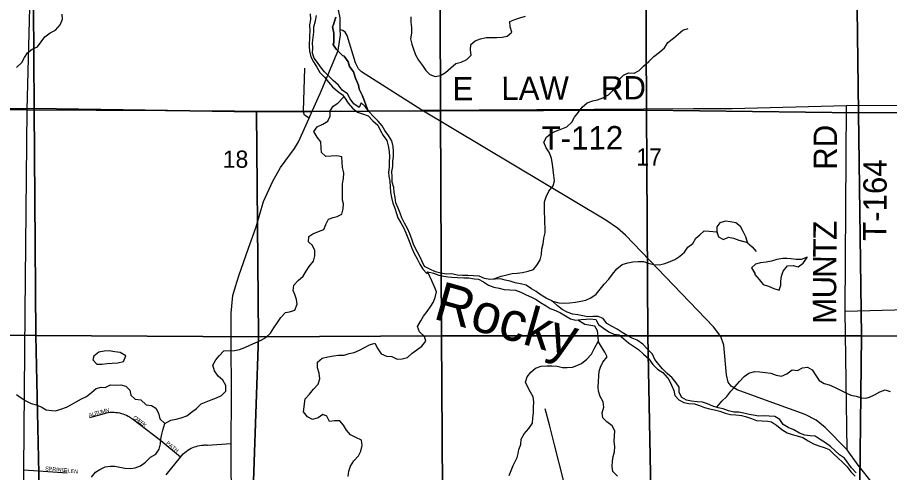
# Model space of a CAD drawing. Extents: x 1985906 to 2277390, y 930619 to 1324581.
# Drawn here: x 2123724 to 2134931, y 1169867 to 1175711 of the extents above; entities that cross this region are included whole.
import ezdxf

# ---------------------------------------------------------------- set-up
doc = ezdxf.new("R2010")
doc.units = 0
for name, color, linetype in [('GM_X_County_Road', 7, 'Continuous'), ('GM_X_Major_River', 7, 'Continuous'), ('GM_X_Major_River_Text', 7, 'Continuous'), ('GM_X_Minor_Lake', 7, 'Continuous'), ('GM_X_Minor_River', 7, 'Continuous'), ('GM_X_Section', 7, 'Continuous'), ('GM_X_Section_Text', 7, 'Continuous'), ('GM_X_State_Route', 7, 'Continuous'), ('GM_X_Township_Road', 7, 'Continuous'), ('GM_X_Township_Road_Text', 7, 'Continuous'), ('GM_X_Township_Subdivision', 7, 'Continuous'), ('GM_X_Township_Subdivision_Text', 7, 'Continuous')]:
    doc.layers.add(name, color=color, linetype=linetype)

msp = doc.modelspace()

# ---------------------------------------------------------------- linework, layer by layer
at = {"layer": 'GM_X_County_Road'}
for points in [[(2123773, 1166123), (2123795, 1166134), (2123816, 1166179), (2123825, 1166243), (2123823, 1166364), (2123796, 1168159), (2123801, 1169024), (2123808, 1169901), (2123825, 1171926), (2123847, 1174524), (2123893, 1176169), (2123892, 1176328), (2123891, 1176487), (2123884, 1177498), (2123887, 1178763), (2123908, 1179927)], [(2134713, 1169730), (2134529, 1169962), (2134386, 1170157), (2134102, 1170445), (2133990, 1170541), (2133849, 1170614), (2133290, 1170814), (2132971, 1170930), (2132894, 1170978), (2132858, 1171030), (2132837, 1171124), (2132801, 1171503), (2132762, 1171615), (2132669, 1171737), (2131538, 1172915), (2131435, 1173007), (2131284, 1173110), (2128920, 1174522), (2128145, 1175013), (2128107, 1175051), (2128070, 1175129), (2127962, 1175480), (2127936, 1175522), (2127906, 1175542), (2127873, 1175554)]]:
    msp.add_lwpolyline(points, dxfattribs=at)
at = {"layer": 'GM_X_Major_River'}
for points in [[(2127485, 1175756), (2127491, 1175687), (2127478, 1175615), (2127480, 1175545), (2127478, 1175470), (2127473, 1175342), (2127477, 1175277), (2127494, 1175207), (2127530, 1175143), (2127570, 1175074), (2127608, 1175006), (2127670, 1174943), (2127721, 1174882), (2127771, 1174820), (2127837, 1174765), (2127903, 1174717), (2127925, 1174684), (2127975, 1174612), (2128029, 1174545), (2128093, 1174493), (2128159, 1174474), (2128231, 1174446), (2128291, 1174385), (2128354, 1174326), (2128386, 1174262), (2128424, 1174196), (2128470, 1174133), (2128490, 1174063), (2128499, 1173992)], [(2128842, 1172735), (2128812, 1172799), (2128792, 1172866), (2128767, 1172932), (2128735, 1173003), (2128697, 1173071), (2128665, 1173138), (2128642, 1173198), (2128616, 1173264), (2128586, 1173331), (2128578, 1173399), (2128567, 1173466), (2128561, 1173528), (2128539, 1173596), (2128540, 1173665), (2128536, 1173733), (2128550, 1173797), (2128547, 1173865), (2128555, 1173926), (2128555, 1173990), (2128552, 1174056), (2128534, 1174129), (2128494, 1174197), (2128446, 1174260), (2128409, 1174318), (2128361, 1174381), (2128305, 1174437), (2128239, 1174504), (2128193, 1174568), (2128141, 1174613), (2128115, 1174557), (2128049, 1174601), (2127999, 1174666), (2127965, 1174730), (2127899, 1174779), (2127848, 1174842), (2127780, 1174900), (2127724, 1174957), (2127670, 1175011), (2127618, 1175078), (2127582, 1175132), (2127538, 1175187), (2127515, 1175253), (2127519, 1175321), (2127517, 1175386), (2127534, 1175522), (2127532, 1175591), (2127553, 1175667), (2127565, 1175737)], [(2128499, 1173992), (2128505, 1173922), (2128501, 1173856), (2128502, 1173789), (2128494, 1173725), (2128498, 1173675), (2128509, 1173609), (2128513, 1173536), (2128519, 1173468), (2128532, 1173399), (2128548, 1173327), (2128572, 1173263), (2128596, 1173194), (2128613, 1173140), (2128651, 1173075), (2128687, 1173013), (2128717, 1172946), (2128742, 1172880), (2128768, 1172816), (2128794, 1172747), (2128824, 1172679), (2128859, 1172612), (2128897, 1172544), (2128933, 1172481), (2128983, 1172425), (2128999, 1172443), (2129071, 1172426), (2129139, 1172404), (2129203, 1172389), (2129253, 1172379), (2129307, 1172377), (2129380, 1172372), (2129460, 1172368), (2129526, 1172367), (2129598, 1172355), (2129648, 1172349), (2129712, 1172316), (2129778, 1172274), (2129848, 1172249), (2129916, 1172235), (2129979, 1172220), (2130051, 1172214), (2130125, 1172210), (2130195, 1172185), (2130261, 1172149), (2130329, 1172120), (2130391, 1172088), (2130445, 1172053), (2130517, 1172008), (2130571, 1171976), (2130637, 1171950), (2130703, 1171919), (2130769, 1171881), (2130833, 1171842), (2130901, 1171822), (2130969, 1171831), (2131034, 1171837), (2131086, 1171841), (2131158, 1171834), (2131192, 1171770), (2131256, 1171721), (2131322, 1171675), (2131388, 1171644), (2131456, 1171636), (2131518, 1171583), (2131578, 1171533), (2131640, 1171490), (2131706, 1171446), (2131769, 1171389), (2131839, 1171326), (2131889, 1171254), (2131951, 1171193), (2132019, 1171150), (2132075, 1171088), (2132095, 1171064), (2132130, 1170991), (2132158, 1170923), (2132174, 1170856), (2132224, 1170800), (2132288, 1170767), (2132352, 1170753), (2132426, 1170750), (2132490, 1170730), (2132554, 1170702), (2132618, 1170685), (2132682, 1170673), (2132751, 1170656), (2132821, 1170630), (2132889, 1170613), (2132955, 1170607), (2133027, 1170599), (2133095, 1170582), (2133159, 1170560), (2133223, 1170537), (2133293, 1170533), (2133366, 1170526), (2133416, 1170518), (2133480, 1170476), (2133546, 1170419), (2133614, 1170378), (2133682, 1170356)], [(2134503, 1169863), (2134442, 1169930), (2134354, 1170051), (2134288, 1170093), (2134230, 1170152), (2134172, 1170200), (2134108, 1170247), (2134040, 1170290), (2133976, 1170336), (2133910, 1170339), (2133842, 1170347), (2133772, 1170371), (2133700, 1170414), (2133630, 1170447), (2133564, 1170483), (2133520, 1170548), (2133456, 1170588), (2133386, 1170591), (2133320, 1170595), (2133252, 1170593), (2133179, 1170606), (2133129, 1170612), (2133057, 1170628), (2132993, 1170641), (2132931, 1170643), (2132863, 1170662), (2132793, 1170686), (2132727, 1170699), (2132661, 1170721), (2132593, 1170750), (2132528, 1170770), (2132458, 1170776), (2132388, 1170785), (2132324, 1170797), (2132260, 1170832), (2132226, 1170894), (2132229, 1170963), (2132189, 1171021), (2132137, 1171084), (2132075, 1171140), (2132015, 1171199), (2131965, 1171255), (2131913, 1171320), (2131884, 1171386), (2131822, 1171453), (2131762, 1171515), (2131690, 1171566), (2131622, 1171593), (2131560, 1171629), (2131496, 1171664), (2131430, 1171708), (2131366, 1171741), (2131298, 1171783), (2131250, 1171846), (2131188, 1171872), (2131120, 1171871), (2131052, 1171867), (2130988, 1171881), (2130924, 1171894), (2130861, 1171900), (2130789, 1171925), (2130725, 1171959), (2130663, 1172008), (2130602, 1172066), (2130519, 1172107), (2130453, 1172145), (2130390, 1172192), (2130330, 1172226), (2130260, 1172273), (2130187, 1172290), (2130121, 1172304), (2130055, 1172326), (2129993, 1172337), (2129931, 1172353), (2129863, 1172352), (2129795, 1172346), (2129725, 1172360), (2129656, 1172389), (2129584, 1172395), (2129512, 1172398), (2129444, 1172396), (2129376, 1172400), (2129306, 1172417), (2129233, 1172415), (2129167, 1172428), (2129095, 1172444), (2129025, 1172477), (2128953, 1172515), (2128919, 1172586), (2128886, 1172658), (2128842, 1172735)], [(2133682, 1170356), (2133746, 1170337), (2133816, 1170317), (2133886, 1170276), (2133954, 1170238), (2134024, 1170211), (2134090, 1170189), (2134154, 1170164), (2134212, 1170106), (2134272, 1170051), (2134328, 1169999), (2134386, 1169942), (2134433, 1169878), (2134489, 1169821)]]:
    msp.add_lwpolyline(points, dxfattribs=at)
at = {"layer": 'GM_X_Minor_Lake'}
for p, q in [((2124706, 1171360), (2124694, 1171315)), ((2125087, 1171295), (2125115, 1171365))]:
    msp.add_line(p, q, dxfattribs=at)
for points in [[(2133105, 1172823), (2133083, 1172894), (2133049, 1172961), (2133017, 1173025), (2132957, 1173074), (2132887, 1173086), (2132823, 1173095), (2132750, 1173073), (2132710, 1173021), (2132712, 1172955)], [(2133104, 1172824), (2133083, 1172894), (2133049, 1172961), (2133017, 1173025), (2132957, 1173074), (2132887, 1173086), (2132823, 1173095), (2132750, 1173073), (2132710, 1173021), (2132712, 1172953)], [(2132710, 1172961), (2132734, 1172894), (2132796, 1172860), (2132862, 1172891), (2132928, 1172879), (2132996, 1172853), (2133110, 1172821)], [(2132712, 1172955), (2132734, 1172894), (2132796, 1172860), (2132862, 1172891), (2132928, 1172879), (2132996, 1172853), (2133105, 1172823)], [(2133874, 1172631), (2133795, 1172605), (2133731, 1172605), (2133661, 1172610), (2133611, 1172614), (2133558, 1172616), (2133484, 1172603), (2133416, 1172583), (2133344, 1172569), (2133273, 1172560), (2133207, 1172542), (2133157, 1172498), (2133201, 1172422)], [(2133872, 1172631), (2133795, 1172605), (2133731, 1172605), (2133661, 1172610), (2133611, 1172614), (2133558, 1172616), (2133484, 1172603), (2133416, 1172583), (2133344, 1172569), (2133273, 1172560), (2133207, 1172542), (2133157, 1172498), (2133199, 1172426)], [(2133200, 1172428), (2133202, 1172411), (2133254, 1172345), (2133308, 1172282), (2133374, 1172262), (2133444, 1172231), (2133514, 1172209), (2133535, 1172273), (2133533, 1172325), (2133541, 1172390), (2133566, 1172454), (2133622, 1172520), (2133692, 1172525), (2133757, 1172511), (2133823, 1172557), (2133872, 1172628)], [(2133201, 1172422), (2133202, 1172411), (2133254, 1172345), (2133308, 1172282), (2133374, 1172262), (2133444, 1172231), (2133514, 1172209), (2133535, 1172273), (2133533, 1172325), (2133541, 1172390), (2133566, 1172454), (2133622, 1172520), (2133692, 1172525), (2133757, 1172511), (2133823, 1172557), (2133874, 1172631)], [(2125115, 1171365), (2125046, 1171409), (2124976, 1171417), (2124904, 1171429), (2124840, 1171428), (2124768, 1171414), (2124706, 1171360)], [(2124694, 1171315), (2124744, 1171259), (2124812, 1171258), (2124877, 1171268), (2124943, 1171274), (2125015, 1171276), (2125087, 1171295)]]:
    msp.add_lwpolyline(points, dxfattribs=at)
at = {"layer": 'GM_X_Minor_River'}
for points in [[(2123711, 1175069), (2123782, 1175131), (2123814, 1175199), (2123853, 1175259), (2123913, 1175305), (2123981, 1175335), (2124078, 1175463), (2124145, 1175513), (2124211, 1175550), (2124274, 1175616), (2124302, 1175690), (2124300, 1175755)], [(2128781, 1175718), (2128780, 1175650), (2128786, 1175582), (2128788, 1175509), (2128777, 1175437), (2128793, 1175369), (2128813, 1175302), (2128838, 1175232), (2128880, 1175161), (2128928, 1175095), (2128970, 1175032), (2129024, 1174978), (2129094, 1174951), (2129162, 1174967), (2129226, 1175005), (2129293, 1175065), (2129359, 1175120), (2129427, 1175136), (2129498, 1175170), (2129556, 1175226), (2129547, 1175292), (2129549, 1175365), (2129607, 1175412), (2129674, 1175438), (2129746, 1175452), (2129818, 1175455), (2129886, 1175455), (2129951, 1175459), (2130019, 1175470), (2130079, 1175524), (2130057, 1175591), (2130050, 1175659), (2130114, 1175687), (2130180, 1175707), (2130253, 1175726)], [(2129846, 1172353), (2129939, 1172389), (2130012, 1172405), (2130080, 1172423), (2130148, 1172426), (2130216, 1172436), (2130287, 1172454), (2130355, 1172475), (2130403, 1172535), (2130440, 1172597), (2130460, 1172666), (2130462, 1172738), (2130479, 1172806), (2130489, 1172876), (2130504, 1172947), (2130504, 1173019), (2130502, 1173069), (2130501, 1173138), (2130497, 1173206), (2130495, 1173276), (2130498, 1173344), (2130518, 1173409), (2130552, 1173479), (2130607, 1173547), (2130627, 1173615), (2130616, 1173681), (2130600, 1173826), (2130585, 1173898), (2130561, 1173971), (2130519, 1174037), (2130489, 1174108), (2130522, 1174174), (2130582, 1174226), (2130650, 1174256), (2130719, 1174281), (2130785, 1174307), (2130848, 1174365), (2130884, 1174429), (2130936, 1174493), (2130981, 1174561), (2131047, 1174617), (2131118, 1174639), (2131180, 1174652), (2131248, 1174680), (2131319, 1174716), (2131377, 1174772), (2131430, 1174840), (2131454, 1174912), (2131512, 1174972), (2131577, 1174998), (2131649, 1174995), (2131715, 1175031), (2131770, 1175087), (2131838, 1175147), (2131903, 1175211), (2131973, 1175265), (2132038, 1175321), (2132082, 1175389), (2132153, 1175447), (2132213, 1175496), (2132275, 1175548), (2132342, 1175570)], [(2125618, 1170496), (2125696, 1170538), (2125763, 1170554), (2125829, 1170568), (2125901, 1170594), (2125962, 1170641), (2126024, 1170691), (2126084, 1170749), (2126151, 1170775), (2126215, 1170799), (2126281, 1170827), (2126348, 1170858), (2126402, 1170914), (2126403, 1170985), (2126365, 1171055), (2126303, 1171104), (2126255, 1171174), (2126233, 1171245), (2126274, 1171313), (2126316, 1171365), (2126377, 1171431), (2126513, 1171434), (2126579, 1171448), (2126644, 1171475), (2126712, 1171505), (2126780, 1171533), (2126847, 1171561), (2126915, 1171602), (2126977, 1171656), (2127020, 1171724), (2127066, 1171796), (2127109, 1171858), (2127169, 1171922), (2127221, 1171932), (2127288, 1171954), (2127318, 1172028), (2127308, 1172090), (2127287, 1172155), (2127267, 1172205), (2127275, 1172275), (2127332, 1172333), (2127396, 1172389), (2127435, 1172453), (2127471, 1172515), (2127528, 1172581), (2127546, 1172652), (2127544, 1172720), (2127517, 1172784), (2127463, 1172829), (2127467, 1172899), (2127521, 1172933), (2127594, 1172961), (2127660, 1172988), (2127686, 1173053), (2127721, 1173123), (2127781, 1173142), (2127831, 1173154), (2127894, 1173186), (2127908, 1173254), (2127916, 1173316), (2127902, 1173367), (2127903, 1173437), (2127901, 1173497), (2127903, 1173574), (2127914, 1173644), (2127918, 1173714), (2127901, 1173785), (2127897, 1173855), (2127891, 1173921), (2127827, 1173934), (2127755, 1173930), (2127685, 1173926), (2127631, 1173975), (2127629, 1174039), (2127621, 1174112), (2127576, 1174176), (2127534, 1174247), (2127576, 1174307), (2127647, 1174340), (2127713, 1174378), (2127741, 1174442), (2127744, 1174513), (2127780, 1174573), (2127842, 1174609), (2127919, 1174692)], [(2130592, 1172070), (2130616, 1172062), (2130680, 1172048), (2130752, 1172041), (2130824, 1172045), (2130896, 1172057), (2130965, 1172070), (2131027, 1172082), (2131093, 1172110), (2131162, 1172160), (2131214, 1172222), (2131264, 1172288), (2131325, 1172350), (2131371, 1172416), (2131426, 1172482), (2131494, 1172539), (2131567, 1172559), (2131633, 1172575), (2131701, 1172578), (2131769, 1172576), (2131831, 1172554), (2131903, 1172537), (2131976, 1172533), (2132042, 1172550), (2132110, 1172576), (2132173, 1172604), (2132237, 1172648), (2132297, 1172696), (2132340, 1172762), (2132404, 1172808), (2132441, 1172876), (2132493, 1172920), (2132547, 1172972), (2132612, 1172967), (2132712, 1172959)], [(2133108, 1172818), (2133164, 1172765), (2133216, 1172707)], [(2127975, 1169817), (2127983, 1169883), (2128006, 1169951), (2128048, 1170017), (2128105, 1170081), (2128135, 1170143), (2128156, 1170216), (2128144, 1170282), (2128074, 1170319), (2128002, 1170351), (2127954, 1170412), (2127914, 1170474), (2127868, 1170531), (2127798, 1170531), (2127734, 1170521), (2127698, 1170590), (2127648, 1170614), (2127588, 1170568), (2127515, 1170547), (2127451, 1170581), (2127400, 1170648), (2127422, 1170812), (2127475, 1170876), (2127527, 1170938), (2127588, 1171004), (2127608, 1171072), (2127603, 1171145), (2127579, 1171213), (2127581, 1171283), (2127642, 1171337), (2127714, 1171355), (2127784, 1171367), (2127848, 1171376), (2127921, 1171374), (2127985, 1171394), (2128053, 1171407), (2128118, 1171441), (2128186, 1171471), (2128250, 1171509), (2128317, 1171528), (2128356, 1171458), (2128398, 1171391), (2128466, 1171361), (2128536, 1171359), (2128602, 1171322), (2128668, 1171328), (2128735, 1171343), (2128797, 1171399), (2128858, 1171443), (2128922, 1171491), (2128974, 1171553), (2128957, 1171613), (2128891, 1171674), (2128867, 1171742), (2128910, 1171816), (2128944, 1171875), (2128990, 1171935), (2129035, 1172003), (2129065, 1172053), (2129090, 1172117), (2129108, 1172189), (2129084, 1172253), (2129051, 1172330), (2128997, 1172441)], [(2131434, 1169821), (2131376, 1169879), (2131368, 1169943), (2131373, 1170013), (2131379, 1170074), (2131395, 1170134), (2131400, 1170202), (2131392, 1170268), (2131398, 1170337), (2131401, 1170405), (2131365, 1170469), (2131297, 1170519), (2131246, 1170569), (2131238, 1170635), (2131258, 1170706), (2131249, 1170774), (2131213, 1170846), (2131193, 1170912), (2131186, 1170963), (2131190, 1171035), (2131196, 1171103), (2131201, 1171168), (2131215, 1171220), (2131247, 1171286), (2131301, 1171353), (2131274, 1171415), (2131230, 1171483), (2131190, 1171547), (2131187, 1171619), (2131177, 1171688), (2131142, 1171748), (2131092, 1171754), (2131016, 1171767), (2130927, 1171825)], [(2130281, 1170963), (2130255, 1171028), (2130274, 1171098), (2130320, 1171156), (2130383, 1171206), (2130455, 1171233), (2130527, 1171237), (2130591, 1171239), (2130660, 1171234), (2130728, 1171216), (2130790, 1171216), (2130856, 1171219), (2130912, 1171243), (2130973, 1171267), (2131043, 1171323), (2131102, 1171387), (2131140, 1171465), (2131186, 1171550)], [(2132713, 1170705), (2132776, 1170784), (2132840, 1170842), (2132891, 1170911), (2132945, 1170969), (2133005, 1171038), (2133063, 1171102), (2133123, 1171142), (2133195, 1171167), (2133263, 1171159), (2133335, 1171151), (2133406, 1171143), (2133476, 1171118), (2133544, 1171104), (2133610, 1171136), (2133678, 1171187), (2133747, 1171179), (2133813, 1171213), (2133875, 1171222), (2133937, 1171186), (2133982, 1171113), (2134026, 1171049), (2134092, 1171009), (2134157, 1170992), (2134223, 1170962), (2134293, 1170928), (2134362, 1170896), (2134432, 1170862), (2134502, 1170848), (2134571, 1170826), (2134625, 1170821), (2134675, 1170837), (2134739, 1170865), (2134805, 1170902), (2134873, 1170930), (2134941, 1170906)], [(2123713, 1170871), (2123772, 1170826), (2123832, 1170790), (2123900, 1170753), (2123965, 1170739), (2124027, 1170710), (2124093, 1170672), (2124165, 1170665), (2124215, 1170661), (2124283, 1170681), (2124353, 1170708), (2124418, 1170740), (2124480, 1170776), (2124549, 1170814), (2124611, 1170844), (2124677, 1170894), (2124736, 1170945), (2124800, 1170965), (2124852, 1170961), (2124918, 1170995), (2124987, 1170988), (2125051, 1170994), (2125115, 1170978), (2125169, 1170927), (2125183, 1170859), (2125238, 1170808), (2125309, 1170802), (2125376, 1170737), (2125445, 1170729), (2125503, 1170696), (2125538, 1170628), (2125554, 1170559), (2125617, 1170496)], [(2130045, 1169828), (2130067, 1169894), (2130096, 1169960), (2130122, 1170010), (2130146, 1170060), (2130159, 1170112), (2130167, 1170162), (2130191, 1170226), (2130196, 1170297), (2130236, 1170365), (2130295, 1170435), (2130345, 1170503), (2130349, 1170571), (2130354, 1170633), (2130354, 1170702), (2130362, 1170774), (2130353, 1170838), (2130317, 1170899), (2130281, 1170963)], [(2125306, 1169954), (2125371, 1170000), (2125435, 1170064), (2125502, 1170104), (2125546, 1170168), (2125562, 1170234), (2125565, 1170294), (2125579, 1170362), (2125591, 1170412), (2125617, 1170497)], [(2124674, 1169809), (2124728, 1169871), (2124783, 1169907), (2124851, 1169942), (2124919, 1169950), (2124975, 1169950), (2125038, 1169937), (2125106, 1169925), (2125176, 1169919), (2125236, 1169928), (2125306, 1169954)]]:
    msp.add_lwpolyline(points, dxfattribs=at)
at = {"layer": 'GM_X_Section'}
for points in [[(2121518, 1177192), (2123921, 1177185), (2123940, 1174541), (2121558, 1174531)], [(2131794, 1177176), (2131810, 1174520), (2129162, 1174511), (2129153, 1177162)], [(2134497, 1177170), (2134532, 1174488), (2131810, 1174520), (2131794, 1177176)], [(2137137, 1177174), (2137149, 1174498), (2134532, 1174488), (2134497, 1177170)], [(2121558, 1174531), (2123940, 1174541), (2123960, 1171627), (2121550, 1171656)], [(2123940, 1174541), (2126796, 1174500), (2126822, 1171608), (2123960, 1171627)], [(2129162, 1174511), (2129172, 1171622), (2126822, 1171608), (2126796, 1174500), (2128229, 1174507)], [(2131810, 1174520), (2131823, 1171622), (2129172, 1171622), (2129162, 1174511)], [(2134532, 1174488), (2134570, 1171622), (2131823, 1171622), (2131810, 1174520)], [(2137149, 1174498), (2137179, 1171610), (2134570, 1171622), (2134532, 1174488)], [(2121550, 1171656), (2123960, 1171627), (2124015, 1169066), (2121561, 1169070)], [(2123960, 1171627), (2126822, 1171608), (2126731, 1169015), (2124015, 1169066)], [(2129172, 1171622), (2129192, 1169001), (2126731, 1169015), (2126822, 1171608)], [(2131823, 1171622), (2131876, 1168970), (2129192, 1169001), (2129172, 1171622)], [(2134570, 1171622), (2134539, 1168995), (2131876, 1168970), (2131823, 1171622)], [(2137179, 1171610), (2137190, 1168963), (2134539, 1168995), (2134570, 1171622)]]:
    msp.add_lwpolyline(points, close=True, dxfattribs=at)
for points in [[(2127817, 1175717), (2127782, 1175608), (2127771, 1175592), (2127790, 1175508), (2127789, 1175481), (2127789, 1175425), (2127789, 1175377), (2127776, 1175370), (2127819, 1175303), (2127858, 1175264), (2127881, 1175243), (2127903, 1175222), (2127922, 1175212), (2127973, 1175143), (2127991, 1175083), (2128043, 1175012), (2128068, 1174930), (2128108, 1174843), (2128114, 1174791), (2128159, 1174705), (2128203, 1174588), (2128229, 1174507), (2126796, 1174500), (2123940, 1174541), (2123921, 1177185)], [(2129153, 1177162), (2129162, 1174511), (2128229, 1174507), (2128203, 1174588), (2128159, 1174705), (2128114, 1174791), (2128108, 1174843), (2128068, 1174930), (2128043, 1175012), (2127991, 1175083), (2127973, 1175143), (2127922, 1175212), (2127903, 1175222), (2127881, 1175243), (2127858, 1175264), (2127819, 1175303), (2127776, 1175370), (2127789, 1175377), (2127789, 1175425), (2127789, 1175481), (2127790, 1175508), (2127771, 1175592), (2127782, 1175608), (2127817, 1175717)]]:
    msp.add_lwpolyline(points, dxfattribs=at)
at = {"layer": 'GM_X_State_Route'}
msp.add_lwpolyline([(2126474, 1169463), (2126469, 1170134), (2126470, 1170242), (2126473, 1170831), (2126472, 1171603), (2126470, 1171914), (2126493, 1172141), (2126528, 1172258), (2126569, 1172393), (2126692, 1172747), (2126792, 1173021), (2126888, 1173347), (2127007, 1173608), (2127104, 1173786), (2127283, 1174030), (2127337, 1174112), (2127472, 1174416), (2127483, 1174441), (2127513, 1174507), (2127616, 1174735), (2127847, 1175288), (2127874, 1175487), (2127873, 1175554), (2127872, 1175706), (2127794, 1176074)], dxfattribs=at)
at = {"layer": 'GM_X_Township_Road'}
for points in [[(2127472, 1174416), (2127415, 1174457), (2127401, 1174497), (2127401, 1174508), (2127416, 1175060)], [(2132908, 1174542), (2134376, 1174582)], [(2134386, 1170157), (2134363, 1171939), (2134376, 1174582)], [(2134376, 1174582), (2135227, 1174585), (2135277, 1174606)], [(2118606, 1174543), (2123847, 1174524), (2127401, 1174508), (2127513, 1174507)], [(2128920, 1174522), (2131135, 1174533), (2132413, 1174540), (2132888, 1174542), (2132908, 1174542)], [(2134363, 1171939), (2139612, 1172079)], [(2130560, 1170481), (2130507, 1170686)], [(2130625, 1170225), (2130560, 1170481), (2130560, 1170481)], [(2130926, 1169045), (2130625, 1170225), (2130625, 1170225)]]:
    msp.add_lwpolyline(points, dxfattribs=at)
at = {"layer": 'GM_X_Township_Subdivision'}
for points in [[(2125818, 1170063), (2125565, 1170275), (2125471, 1170349), (2125203, 1170551), (2125194, 1170558), (2125184, 1170565), (2125175, 1170571), (2125166, 1170577), (2125158, 1170581), (2125146, 1170588), (2125127, 1170598), (2125106, 1170607), (2125083, 1170616), (2125064, 1170622), (2125039, 1170628), (2125013, 1170633), (2124990, 1170636), (2124966, 1170638), (2124943, 1170638), (2124917, 1170637), (2124888, 1170633), (2124863, 1170629), (2124837, 1170622), (2124649, 1170568)], [(2125634, 1169837), (2125818, 1170063), (2125837, 1170087), (2125855, 1170106), (2125876, 1170125), (2125892, 1170138), (2125912, 1170153), (2125933, 1170166), (2125957, 1170179), (2125977, 1170189), (2126001, 1170198), (2126020, 1170204), (2126044, 1170211), (2126067, 1170216), (2126094, 1170220), (2126119, 1170221), (2126131, 1170222), (2126146, 1170222), (2126153, 1170221), (2126160, 1170221), (2126168, 1170221), (2126470, 1170242)], [(2123808, 1169901), (2124364, 1169862)]]:
    msp.add_lwpolyline(points, dxfattribs=at)

# ---------------------------------------------------------------- texts
at = {"layer": 'GM_X_Major_River_Text'}
msp.add_text('Rocky', height=500.2, rotation=344.186, dxfattribs=at).set_placement((2129054, 1171846))
at = {"layer": 'GM_X_Section_Text'}
for s, p in [('18', (2126362, 1173781)), ('17', (2131677, 1173810))]:
    msp.add_text(s, height=221, rotation=0, dxfattribs=at).set_placement(p)
at = {"layer": 'GM_X_Township_Road_Text'}
for s, rotation, p in [('E', 0, (2129314, 1174646)), ('LAW', 0.2863, (2129943, 1174651)), ('RD', 0.4936, (2131223, 1174655)), ('T-112', 0.2807, (2130461, 1174012)), ('RD', 90, (2134256, 1173754)), ('T-164', 89.7193, (2134891, 1172841)), ('Z', 89.5586, (2134250, 1172855)), ('T', 89.5565, (2134249, 1172630)), ('N', 89.5592, (2134246, 1172366)), ('U', 89.592, (2134245, 1172102)), ('M', 90.5435, (2134248, 1171778))]:
    msp.add_text(s, height=300, rotation=rotation, dxfattribs=at).set_placement(p)
at = {"layer": 'GM_X_Township_Subdivision_Text'}
for s, rotation, p in [('A', 16.1885, (2124648, 1170577)), ('U', 16.1675, (2124690, 1170590)), ('T', 16.1989, (2124732, 1170602)), ('U', 16.1913, (2124766, 1170612)), ('M', 15.8829, (2124808, 1170624)), ('N', 7.2769, (2124857, 1170638)), ('C', 321.2112, (2125204, 1170565)), ('R', 323.2333, (2125236, 1170539)), ('E', 323.3388, (2125268, 1170516)), ('E', 323.3388, (2125296, 1170495)), ('K', 323.346, (2125325, 1170474)), ('PATH', 320.596, (2125629, 1170237)), ('SPRING', 355.3312, (2124079, 1169896)), ('GLEN', 352.0909, (2124313, 1169878))]:
    msp.add_text(s, height=50, rotation=rotation, dxfattribs=at).set_placement(p)

doc.saveas('drawing.dxf')
